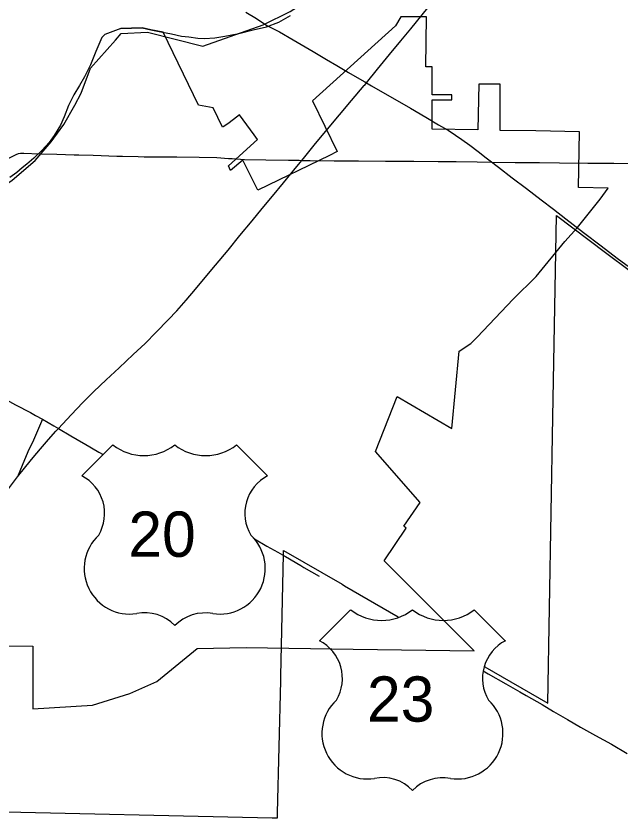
# Model space of a CAD drawing. Extents: x -232 to 448, y 619 to 1059.
# Drawn here: x 147.98 to 160.32, y 883.83 to 900.18 of the extents above; entities that cross this region are included whole.
import ezdxf

# ---------------------------------------------------------------- set-up
doc = ezdxf.new("R2010")
doc.units = 0
doc.layers.add('Default', color=7, linetype='Continuous')

msp = doc.modelspace()

# ---------------------------------------------------------------- linework, layer by layer
at = {"layer": 'Default'}
for p, q in [((155.833, 900.164), (155.718, 899.979)), ((156.353, 900.169), (155.833, 900.164)), ((156.343, 899.146), (156.353, 900.169)), ((155.718, 899.979), (154.029, 898.45)), ((156.467, 899.146), (156.343, 899.146)), ((156.467, 898.578), (156.467, 899.146)), ((157.421, 898.79), (157.398, 897.858)), ((157.854, 898.79), (157.421, 898.79)), ((157.854, 897.849), (157.854, 898.79)), ((154.029, 898.45), (154.532, 897.416)), ((156.467, 897.876), (156.467, 898.475)), ((152.001, 898.312), (151.699, 898.366)), ((152.841, 897.76), (152.538, 898.166)), ((152.608, 897.241), (152.358, 897.029)), ((152.91, 896.634), (152.608, 897.241)), ((160.061, 896.673), (159.451, 896.684)), ((156.867, 891.769), (157.019, 893.349)), ((149.957, 891.436), (149.322, 890.802)), ((149.957, 891.436), (149.322, 890.802)), ((153.112, 890.802), (152.477, 891.436)), ((153.112, 890.802), (152.477, 891.436)), ((155.894, 889.775), (156.222, 890.26)), ((155.939, 889.737), (155.894, 889.775)), ((155.49, 889.071), (155.939, 889.737)), ((154.806, 888.074), (154.172, 887.439)), ((154.806, 888.074), (154.172, 887.439)), ((157.961, 887.439), (157.327, 888.074)), ((157.961, 887.439), (157.327, 888.074)), ((147.3, 887.337), (148.326, 887.33)), ((148.326, 887.33), (148.322, 886.051)), ((151.678, 887.285), (152.672, 887.302)), ((154.858, 887.269), (157.326, 887.235))]:
    msp.add_line(p, q, dxfattribs=at)
for points in [[(150.008, 899.693), (150.127, 899.825), (150.661, 899.855), (151.788, 899.57), (153.018, 900.005), (153.569, 900.276), (154.116, 900.626), (154.492, 901.156), (154.678, 901.743), (154.682, 902.32), (154.74, 902.84), (154.994, 903.366), (155.211, 903.656)], [(155.092, 898.774), (155.129, 898.818), (155.357, 899.099), (155.598, 899.397), (155.83, 899.676), (156.031, 899.924), (156.263, 900.204), (156.47, 900.461), (156.736, 900.775), (156.996, 901.089), (157.142, 901.265)], [(152.668, 900.264), (152.887, 900.135), (153.098, 899.992), (153.356, 899.858), (153.634, 899.696), (154.039, 899.458), (154.315, 899.299), (154.522, 899.174), (154.764, 899.032), (154.986, 898.903), (155.098, 898.838)], [(150.552, 899.94), (150.727, 899.9), (150.965, 899.854), (151.153, 899.816), (151.357, 899.775), (151.505, 899.758), (151.689, 899.732), (151.825, 899.723), (152.032, 899.738), (152.236, 899.769), (152.523, 899.829), (152.817, 899.898), (153.086, 899.965), (153.34, 900.055), (153.581, 900.191)], [(150.116, 899.927), (149.79, 899.803), (149.732, 899.742), (149.608, 899.462), (149.5, 899.189), (149.378, 898.942), (149.276, 898.768), (149.158, 898.574), (149.047, 898.359), (148.964, 898.128), (148.888, 897.954), (148.761, 897.745), (148.659, 897.605), (148.507, 897.438), (148.343, 897.283), (148.202, 897.159), (148.107, 897.084), (147.997, 896.991), (147.851, 896.892)], [(150.116, 899.927), (149.79, 899.803), (149.732, 899.742), (149.608, 899.462), (149.5, 899.189), (149.378, 898.942), (149.276, 898.768), (149.158, 898.574), (149.047, 898.359), (148.964, 898.128), (148.888, 897.954), (148.761, 897.745), (148.659, 897.605), (148.507, 897.438), (148.343, 897.283), (148.202, 897.159), (148.107, 897.084), (147.997, 896.991), (147.851, 896.892)], [(150.552, 899.94), (150.116, 899.927)], [(150.116, 899.927), (150.552, 899.94)], [(150.98, 899.851), (150.727, 899.9), (150.552, 899.94)], [(151.699, 898.366), (150.98, 899.851)], [(143.034, 895.104), (143.396, 895.497), (143.873, 896.044), (144.079, 896.251), (144.599, 896.638), (145.221, 896.704), (145.994, 896.599), (146.382, 896.489), (146.827, 896.265), (147.398, 896.5), (147.899, 896.832), (148.367, 897.234), (148.696, 897.615), (148.953, 897.968), (149.178, 898.362), (149.309, 898.607), (149.499, 899.12), (150.008, 899.693)], [(153.777, 897.197), (153.811, 897.239), (153.868, 897.309), (154.09, 897.58), (154.335, 897.872), (154.578, 898.164), (154.822, 898.457), (155.084, 898.765), (155.092, 898.774)], [(155.098, 898.838), (155.229, 898.761), (155.554, 898.578), (155.803, 898.432), (156.025, 898.303), (156.337, 898.122), (156.601, 897.965), (156.78, 897.86)], [(156.467, 898.475), (156.871, 898.47), (156.873, 898.576), (156.467, 898.578)], [(152.194, 897.913), (152.001, 898.312)], [(152.538, 898.166), (152.476, 898.117), (152.326, 898.003), (152.222, 897.93), (152.194, 897.913)], [(157.398, 897.858), (156.467, 897.876)], [(156.78, 897.86), (156.794, 897.852), (156.947, 897.755), (157.077, 897.661), (157.234, 897.546), (157.41, 897.416), (157.569, 897.293), (157.654, 897.228)], [(158.586, 897.839), (157.854, 897.849)], [(159.473, 897.822), (158.586, 897.839)], [(159.451, 896.684), (159.473, 897.822)], [(152.358, 897.029), (152.313, 897.125), (152.903, 897.662), (152.841, 897.76)], [(147.219, 896.988), (147.239, 896.998), (147.613, 897.179), (147.982, 897.361), (148.032, 897.376), (148.073, 897.383), (148.142, 897.383), (148.459, 897.375), (148.815, 897.366), (149.169, 897.353)], [(149.169, 897.353), (149.262, 897.35), (149.556, 897.342), (150.034, 897.326), (150.155, 897.323)], [(150.155, 897.323), (150.468, 897.315), (150.593, 897.313)], [(150.593, 897.313), (150.784, 897.311), (151.257, 897.311), (151.717, 897.301), (152.078, 897.296), (152.315, 897.279), (152.392, 897.274)], [(154.532, 897.416), (154.373, 897.338), (152.91, 896.634)], [(149.401, 892.358), (149.57, 892.524), (149.822, 892.762), (150.084, 893.008), (150.369, 893.276), (150.611, 893.506), (150.837, 893.732), (151.085, 893.986), (151.26, 894.171), (151.452, 894.39), (151.64, 894.609), (151.836, 894.846), (152.049, 895.104), (152.305, 895.408), (152.548, 895.705), (152.799, 896.005), (153.002, 896.255), (153.215, 896.508), (153.437, 896.778), (153.65, 897.041), (153.777, 897.197)], [(152.392, 897.274), (152.64, 897.258), (153.075, 897.249), (153.537, 897.243), (153.756, 897.24)], [(153.756, 897.24), (153.811, 897.239), (153.983, 897.236), (154.471, 897.227), (154.927, 897.227)], [(154.927, 897.227), (154.964, 897.227), (155.514, 897.223), (155.985, 897.222)], [(155.985, 897.222), (156.097, 897.222), (156.591, 897.216), (156.961, 897.214), (157.384, 897.207), (157.686, 897.203)], [(157.654, 897.228), (157.825, 897.097), (158.098, 896.883), (158.393, 896.666), (158.693, 896.432), (158.942, 896.24), (159.194, 896.045), (159.559, 895.764), (159.916, 895.498), (160.245, 895.245), (160.572, 895.006)], [(157.686, 897.203), (158.165, 897.195), (158.656, 897.193), (159.063, 897.187), (159.645, 897.18), (160.177, 897.178), (160.702, 897.177), (161.148, 897.17), (161.6, 897.164), (161.708, 897.163), (161.828, 897.148), (162.095, 897.108), (162.513, 897.044), (162.926, 896.971), (163.278, 896.913), (163.51, 896.88), (163.901, 896.817), (164.264, 896.752), (164.425, 896.731), (164.573, 896.711), (164.706, 896.712), (164.996, 896.704), (165.179, 896.704)], [(157.019, 893.349), (157.255, 893.506), (157.388, 893.629), (158.12, 894.407), (158.587, 894.869), (159.175, 895.584), (159.436, 895.868), (159.898, 896.448), (160.061, 896.673)], [(158.826, 886.166), (158.927, 891.998), (159.002, 896.114)], [(159.002, 896.114), (160.002, 895.358), (160.084, 895.296), (160.78, 894.779)], [(147.479, 892.522), (147.724, 892.389), (147.972, 892.253), (148.275, 892.093), (148.38, 892.035)], [(155.313, 891.298), (155.753, 892.42)], [(155.753, 892.42), (156.867, 891.769)], [(148.843, 891.772), (149.104, 892.049), (149.34, 892.297), (149.401, 892.358)], [(148.523, 891.957), (148.419, 891.723), (148.316, 891.486), (148.243, 891.34), (148.153, 891.133), (148.011, 890.781)], [(148.38, 892.035), (148.523, 891.957), (148.752, 891.825)], [(148.752, 891.825), (148.843, 891.772)], [(148.793, 891.715), (148.843, 891.772)], [(148.843, 891.772), (149.099, 891.621), (149.355, 891.473)], [(145.406, 887.392), (145.524, 887.551), (145.737, 887.825), (145.917, 888.061), (146.102, 888.298), (146.298, 888.552), (146.485, 888.796), (146.701, 889.08), (146.915, 889.354), (147.15, 889.666), (147.381, 889.967), (147.607, 890.259), (147.823, 890.539), (148.011, 890.781), (148.181, 890.994), (148.331, 891.175), (148.478, 891.354), (148.643, 891.543), (148.793, 891.715)], [(149.355, 891.473), (149.369, 891.464), (149.669, 891.29), (149.759, 891.238)], [(156.222, 890.26), (155.313, 891.298)], [(152.843, 889.516), (153.095, 889.373), (153.32, 889.245)], [(153.313, 883.826), (153.314, 883.878), (153.315, 883.933), (153.379, 886.62), (153.379, 886.634), (153.381, 886.727), (153.437, 889.199), (153.439, 889.284)], [(153.439, 889.284), (154.631, 888.592), (154.682, 888.562), (155.778, 887.927)], [(153.32, 889.245), (153.414, 889.192)], [(153.414, 889.192), (153.475, 889.157), (153.787, 888.973)], [(153.787, 888.973), (153.852, 888.934), (154.163, 888.76)], [(157.326, 887.235), (155.49, 889.071)], [(150.853, 886.607), (151.678, 887.285)], [(152.672, 887.302), (154.858, 887.269)], [(157.51, 886.83), (157.613, 886.769), (157.971, 886.565), (158.257, 886.397), (158.384, 886.325)], [(157.54, 886.906), (158.826, 886.166)], [(148.322, 886.051), (149.543, 886.128), (150.303, 886.363), (150.853, 886.607)], [(158.384, 886.325), (158.712, 886.137)], [(158.712, 886.137), (158.946, 885.999), (159.228, 885.834), (159.498, 885.681), (159.804, 885.509), (160.125, 885.33), (160.449, 885.143)], [(147.083, 883.968), (147.168, 883.966), (153.208, 883.829), (153.313, 883.826)]]:
    msp.add_lwpolyline(points, dxfattribs=at)
for centre, radius, start, end in [((150.587, 892.237), 1.019, 231.813, 308.187), ((150.587, 892.237), 1.019, 231.813, 308.187), ((151.847, 892.237), 1.019, 231.813, 308.187), ((151.847, 892.237), 1.019, 231.813, 308.187), ((148.926, 890.037), 0.862, 329.1175, 62.6108), ((148.926, 890.037), 0.862, 329.1175, 62.6108), ((153.508, 890.037), 0.862, 117.3892, 210.8825), ((153.508, 890.037), 0.862, 117.3892, 210.8825), ((150.3, 888.914), 0.93, 133.0046, 278.7282), ((150.3, 888.914), 0.93, 133.0046, 278.7282), ((152.134, 888.914), 0.93, 261.2718, 46.9954), ((152.134, 888.914), 0.93, 261.2718, 46.9954), ((150.613, 887.18), 0.832, 43.4177, 101.8742), ((150.613, 887.18), 0.832, 43.4177, 101.8742), ((151.839, 887.125), 0.883, 79.9613, 134.7468), ((151.839, 887.125), 0.883, 79.9613, 134.7468), ((155.437, 888.875), 1.019, 231.813, 308.187), ((155.437, 888.875), 1.019, 231.813, 308.187), ((156.697, 888.875), 1.019, 231.813, 308.187), ((156.697, 888.875), 1.019, 231.813, 308.187), ((153.775, 886.674), 0.862, 329.1175, 62.6108), ((153.775, 886.674), 0.862, 329.1175, 62.6108), ((158.358, 886.674), 0.862, 117.3892, 210.8825), ((158.358, 886.674), 0.862, 117.3892, 210.8825), ((155.15, 885.551), 0.93, 133.0046, 278.7282), ((155.15, 885.551), 0.93, 133.0046, 278.7282), ((156.984, 885.551), 0.93, 261.2718, 46.9954), ((156.984, 885.551), 0.93, 261.2718, 46.9954), ((155.462, 883.817), 0.832, 43.4177, 101.8742), ((155.462, 883.817), 0.832, 43.4177, 101.8742), ((156.688, 883.762), 0.883, 79.9613, 134.7468), ((156.688, 883.762), 0.883, 79.9613, 134.7468)]:
    msp.add_arc(centre, radius, start, end, dxfattribs=at)

# ---------------------------------------------------------------- texts
for s, p in [('20', (150.272, 889.153)), ('23', (155.14, 885.79))]:
    msp.add_text(s, height=0.9234, dxfattribs=at).set_placement(p)

doc.saveas('drawing.dxf')
